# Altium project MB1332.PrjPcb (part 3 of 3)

## Sheet Power_Board.SchDoc: Board_Power
size A4; Date: Not used; ApprovedBy: Not used; CheckedBy: Not used; Author: Not used; CompanyName: STMicroelectronics; DrawnBy: Not used; Engineer: Not used; Organization: Not used; Address1: Not used; Address2: Not used; Address3: Not used; Address4: Not used; DocumentNumber: Not used; Revision: Not used; SheetNumber: 15; SheetTotal: 17
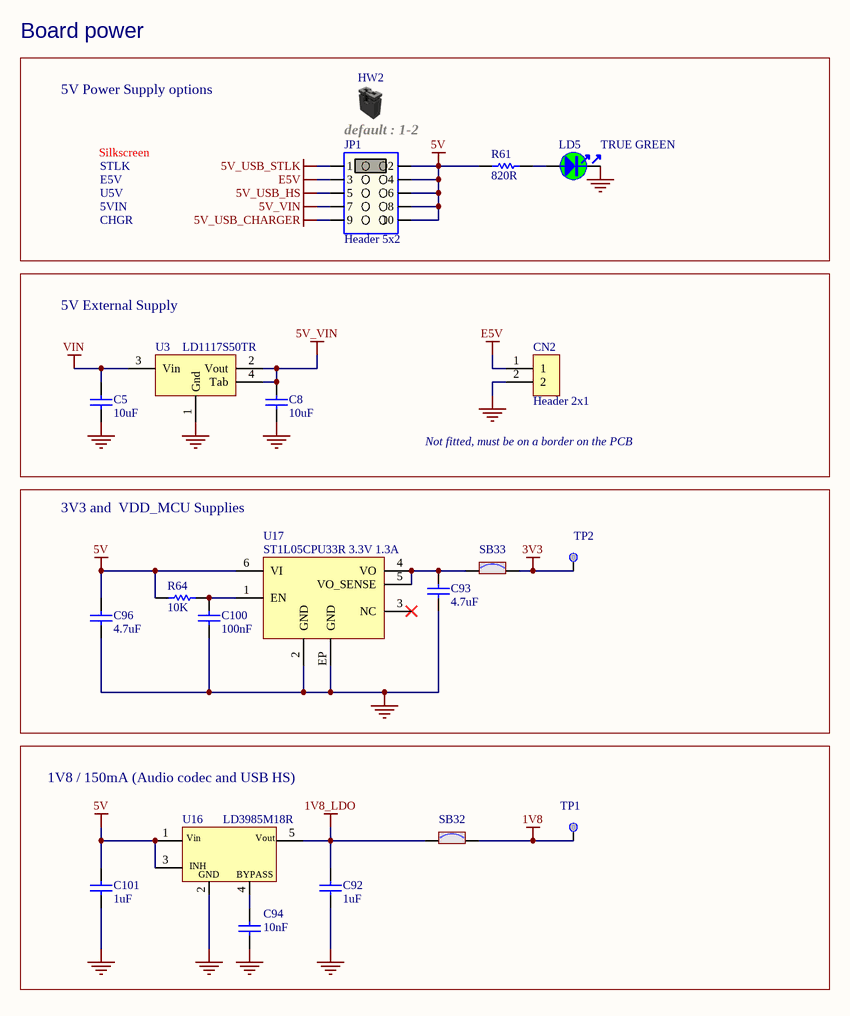
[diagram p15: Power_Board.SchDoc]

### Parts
C5  value 10uF  [C0805]  (hidden comment: Capacitor)
C8  value 10uF  [C0805]  (hidden comment: Capacitor)
C92  value 1uF  [C0402]  (hidden comment: Capacitor)
C93  value 4.7uF  [C0603]  (hidden comment: Capacitor)
C94  value 10nF  [C0402]  (hidden comment: Capacitor)
C96  value 4.7uF  [C0603]  (hidden comment: Capacitor)
C100  value 100nF  [C0402]  (hidden comment: Capacitor)
C101  value 1uF  [C0402]  (hidden comment: Capacitor)
CN2  Header 2x1  [CON_SAMTEC_TSW-102-07-G-S]
HW2  Shunt Black 2.54mm  (value not drawn)  (mechanical)
JP1  value Header 5x2  [CON_SAMTEC_TSM-105-01-L-DV]  (hidden comment: Jumper_Header 5x2 Fitted 1-2)
LD5  value TRUE GREEN  [LED_0603_VISHAY_VLMTG1300-GS08_GREEN_1A2K_H0P8]  (hidden comment: LED_green)
R61  value 820R  [R0603]  (hidden comment: Resistor)
R64  value 10K  [R0402]  (hidden comment: Resistor)
SB32  SB_ON  [SOLDER-BRIDGE_R0603-0R]  (value not drawn)
SB33  SB_ON  [SOLDER-BRIDGE_R0603-0R]  (value not drawn)
TP1  Test Point  [TP_SMD_2MM]  (value not drawn)  (no BOM)
TP2  Test Point  [TP_SMD_2MM]  (value not drawn)  (no BOM)
U3  LD1117S50TR  [REG_SOT223-TAB]
U16  LD3985M18R  [REG_SOT23-5L]
U17  value ST1L05CPU33R 3.3V 1.3A  [ICC_DFN6-EPAD_3X3_P095]  (hidden comment: ST1L05CPU33R)

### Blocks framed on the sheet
Board power: HW2 JP1 LD5 R61
5V External Supply: C5 C8 CN2 U3
3V3 and  VDD_MCU Supplies: C93 C96 C100 R64 SB33 TP2 U17
1V8 / 150mA (Audio codec and USB HS): C92 C94 C101 SB32 TP1 U16

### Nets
1V8: SB32.2 TP1.1
1V8_LDO: C92.2 SB32.1 U16.5(Vout)
3V3: SB33.2 TP2.1
5V: C96.2 C101.2 JP1.2 JP1.4 JP1.6 JP1.8 JP1.10 R61.1 R64.1 U16.1(Vin) U16.3(CE) U17.6(VI)
5V_USB_CHARGER: JP1.9
5V_USB_HS: JP1.5
5V_USB_STLK: JP1.1
5V_VIN: C8.2 JP1.7 U3.2(Vout) U3.4(Tab)
E5V: CN2.1 JP1.3
GND: C5.1 C8.1 C92.1 C93.1 C94.1 C96.1 C100.1 C101.1 CN2.2 LD5.2 U3.1(Gnd) U16.2(GND) U17.2(GND) U17.EP(GND)
VIN: C5.2 U3.3(Vin)
NetC93_2: C93.2 SB33.1 U17.4(VO) U17.5(VO_SENSE)
NetC94_2: C94.2 U16.4(BYPASS)
NetC100_2: C100.2 R64.2 U17.1(EN)
NetLD5_1: LD5.1 R61.2

Not connected (* = marked no-connect by the designer): U17 3(NC)*

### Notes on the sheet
- 5V Power Supply options
- Silkscreen
- default : 1-2
- STLK
- E5V
- U5V
- 5VIN
- CHGR
- Not fitted, must be on a border on the PCB

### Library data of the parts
C5 C8 = MCD-00014: Capacitor, MLCC, 10uF, 25V, X5R, 10%, 0805, T=0,85mm; Manufacturer_Part_Number: CC0805KRX5R8BB106; Manufacturer: YAGEO; Provided_By: SUBCO
C92 C101 = MCD-00095: Capacitor, MLCC, 1uF, 6V3, X5R, 10%, 0402, T=0,5mm; Manufacturer_Part_Number: GRM155R61E105KA12; Manufacturer: MURATA; Alternate_Manufacturer_Part_Number: GRM155R60J105KE19; Provided_By: SUBCO
C93 C96 = MCD-00009: Capacitor, MLCC, 4.7uF, 16V, X5R, 10%, 0603, T=0.8mm; Manufacturer_Part_Number: CC0603KRX5R7BB475; Manufacturer: YAGEO; Provided_By: SUBCO
C94 = MCD-00011: Capacitor, MLCC, 10nF, 16V, X7R, 10%, 0402, T=0.5mm; Manufacturer_Part_Number: CC0402KRX7R7BB103; Manufacturer: YAGEO; Provided_By: SUBCO
C100 = MCD-00006: Capacitor, MLCC, 100nF, 16V, X7R, 10%, 0402, T=0.5mm; Manufacturer_Part_Number: CC0402KRX7R7BB104; Manufacturer: YAGEO; Alternate_Manufacturer_Part_Number: GCM155R71C104KA55D; Alternate_Manufacturer: MURATA; Provided_By: SUBCO
CN2 = MCD-00032: Header, 2x1, 2,54mm, VR, TH, Height 5.84mm/2.54mm; Part_Type: Connector; Manufacturer_Part_Number: TSW-102-07-G-S; Manufacturer: SAMTEC; Alternate_Manufacturer_Part_Number: 313102S111116; Alternate_Manufacturer: JIUBABA; Part_Preference: Recommended
HW2 = MCD-00043: SHUNT 2.54mm BLACK; Part_Type: Mechanical; Manufacturer: SAMTEC; Alternate_Manufacturer_Part_Number: 316102S111A; Alternate_Manufacturer: JIUBABA; Value: SNT-100-BK-G; Provided_By: SUBCO
JP1 = MCD-01230: Header, 5x2, 2.54mm, VR, SMT, Height 5.84mm; Part_Type: Connector; Manufacturer_Part_Number: TSM-105-01-L-DV; Manufacturer: SAMTEC; Alternate_Manufacturer_Part_Number: PHFM25-1205G0B116T1; Alternate_Manufacturer: JIUBABA; Provided_By: SUBCO
LD5 = MCD-00589: LED Green, 0603 SMD, Fw Voltage = 2.8V - 3.6V; Part_Type: Display; Manufacturer_Part_Number: VLMTG1300-GS08; Manufacturer: VISHAY; Alternate_Manufacturer_Part_Number: LG Q396-PS-35; Alternate_Manufacturer: OSRAM OPTO SEMICONDUCTORS; Order_Code_RS: 7730452; Provided_By: SUBCO
R61 = MCD-00528: Resistor,820R,0603,1%,1/10W; Manufacturer_Part_Number: RC0603FR-07820RL; Manufacturer: YAGEO; BMS_Part_Number: 9129759; Provided_By: SUBCO
R64 = MCD-00053: Resistor,10K,0402,1%,1/16W; Manufacturer_Part_Number: RC0402FR-0710KL; Manufacturer: YAGEO; Provided_By: SUBCO
SB32 SB33 = MCD-00071: Solder Bridge ON; Part_Type: Mechanical; Manufacturer_Part_Number: RC0603JR-070RL; Manufacturer: YAGEO; Provided_By: SUBCO
TP1 TP2 = MCD-00177: Test Point 2mm; Part_Type: Mechanical
U3 = MCD-00088: IC REG LDO 5V 0.8A SOT223; Manufacturer: STMICROELECTRONICS; BMS_Part_Number: 9176133; Provided_By: SUBCO with ST control
U16 = MCD-00078: Ultra low drop-low noise BiCMOS voltage, regulators low ESR capacitors compatible; Manufacturer: STMICROELECTRONICS; Part_Type: IC; BMS_Part_Number: 9176159; Provided_By: SUBCO with ST control
U17 = MCD-01025: LDO, 3.3V, 1.3A, Very low quiescent current BiCMOS voltage regulator; Part_Type: IC; Manufacturer: STMICROELECTRONICS; BMS_Part_Number: 9176246; Provided_By: SUBCO with ST control

## Sheet Power_MCU.SchDoc: MCU_Power
size A4; Date: Not used; ApprovedBy: Not used; CheckedBy: Not used; Author: Not used; CompanyName: STMicroelectronics; DrawnBy: Not used; Engineer: Not used; Organization: Not used; Address1: Not used; Address2: Not used; Address3: Not used; Address4: Not used; DocumentNumber: Not used; Revision: Not used; SheetNumber: 14; SheetTotal: 17
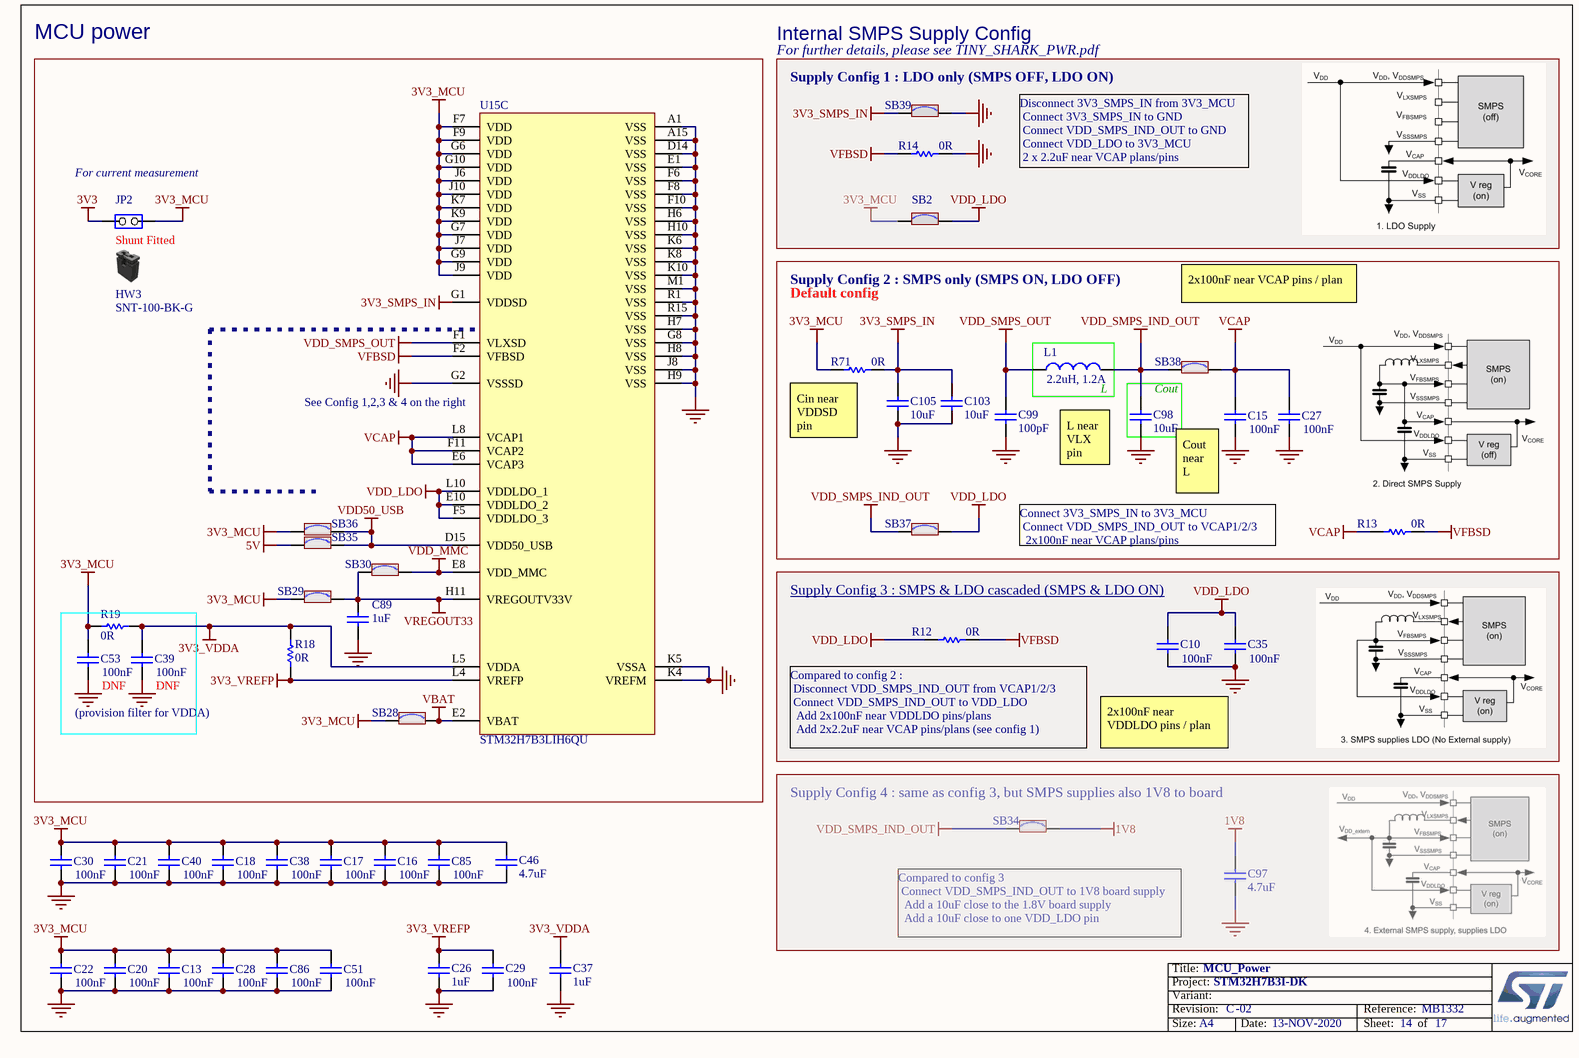
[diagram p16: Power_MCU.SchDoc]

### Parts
C10  value 100nF  [C0402]  (hidden comment: Capacitor)
C13  value 100nF  [C0402]  (hidden comment: Capacitor)
C15  value 100nF  [C0402]  (hidden comment: Capacitor)
C16  value 100nF  [C0402]  (hidden comment: Capacitor)
C17  value 100nF  [C0402]  (hidden comment: Capacitor)
C18  value 100nF  [C0402]  (hidden comment: Capacitor)
C20  value 100nF  [C0402]  (hidden comment: Capacitor)
C21  value 100nF  [C0402]  (hidden comment: Capacitor)
C22  value 100nF  [C0402]  (hidden comment: Capacitor)
C26  value 1uF  [C0402]  (hidden comment: Capacitor)
C27  value 100nF  [C0402]  (hidden comment: Capacitor)
C28  value 100nF  [C0402]  (hidden comment: Capacitor)
C29  value 100nF  [C0402]  (hidden comment: Capacitor)
C30  value 100nF  [C0402]  (hidden comment: Capacitor)
C35  value 100nF  [C0402]  (hidden comment: Capacitor)
C37  value 1uF  [C0402]  (hidden comment: Capacitor)
C38  value 100nF  [C0402]  (hidden comment: Capacitor)
C39  value 100nF  [C0402]  (hidden comment: Capacitor)
C40  value 100nF  [C0402]  (hidden comment: Capacitor)
C46  value 4.7uF  [C0603]  (hidden comment: Capacitor)
C51  value 100nF  [C0402]  (hidden comment: Capacitor)
C53  value 100nF  [C0402]  (hidden comment: Capacitor)
C85  value 100nF  [C0402]  (hidden comment: Capacitor)
C86  value 100nF  [C0402]  (hidden comment: Capacitor)
C89  value 1uF  [C0603]  (hidden comment: Capacitor)
C97  value 4.7uF  [C0603]  (hidden comment: Capacitor)
C98  value 10uF  [C0603]  (hidden comment: Capacitor)
C99  value 100pF  [C0402]  (hidden comment: Capacitor)
C103  value 10uF  [C0402]  (hidden comment: Capacitor)
C105  value 10uF  [C0402]  (hidden comment: Capacitor)
HW3  value SNT-100-BK-G  (hidden comment: Shunt Black 2.54mm)  (mechanical)
JP2  Jumper_Header 2x1  [CON_SAMTEC_TSW-102-07-G-S]  (value not drawn)
L1  value 2.2uH, 1.2A  [L0805_H0P9]  (hidden comment: Inductor)
R12  value 0R  [R0402]  (hidden comment: Resistor)
R13  value 0R  [R0402]  (hidden comment: Resistor)
R14  value 0R  [R0402]  (hidden comment: Resistor)
R18  value 0R  [R0603]  (hidden comment: Resistor)
R19  value 0R  [R0603]  (hidden comment: Resistor)
R71  value 0R  [R0603]  (hidden comment: Resistor)
SB2  SB_ON  [SOLDER-BRIDGE_R0603-0R]  (value not drawn)
SB28  SB_ON  [SOLDER-BRIDGE_R0603-0R]  (value not drawn)
SB29  SB_ON  [SOLDER-BRIDGE_R0603-0R]  (value not drawn)
SB30  SB_ON  [SOLDER-BRIDGE_R0603-0R]  (value not drawn)
SB34  SB_ON  [SOLDER-BRIDGE_R0603-0R]  (value not drawn)
SB35  SB_ON  [SOLDER-BRIDGE_R0603-0R]  (value not drawn)
SB36  SB_ON  [SOLDER-BRIDGE_R0603-0R]  (value not drawn)
SB37  SB_ON  [SOLDER-BRIDGE_R0603-0R]  (value not drawn)
SB38  SB_ON  [SOLDER-BRIDGE_R0603-0R]  (value not drawn)
SB39  SB_ON  [SOLDER-BRIDGE_R0603-0R]  (value not drawn)
U15  value STM32H7B3LIH6QU  [ICC_TFBGA225_13X13_STM32H7B3NIH6Q_P080]  (hidden comment: STM32H7B3NIH6Q)  (part C of 3)

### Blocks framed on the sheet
MCU power: C39 C53 C89 HW3 JP2 R18 R19 SB28-SB30 SB35 SB36 U15
Internal SMPS Supply Config: R14 SB2 SB39
L: L1
Cout: C98
Supply Config 3 : SMPS & LDO cascaded (SMPS & LDO ON): C10 C35 R12

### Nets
1V8: C97.2 SB34.1
3V3: JP2.1(COMMON)
3V3_MCU: C13.1 C16.1 C17.1 C18.1 C20.1 C21.1 C22.1 C28.1 C30.1 C38.1 C40.1 C46.2 C51.1 C53.1 C85.1 C86.1 JP2.2(NO) R19.1 R71.1 SB2.2 SB28.1 SB29.1 SB36.1 U15.F7(VDD) U15.F9(VDD) U15.G6(VDD) U15.G7(VDD) U15.G9(VDD) U15.G10(VDD) U15.J6(VDD) U15.J7(VDD) U15.J9(VDD) U15.J10(VDD) U15.K7(VDD) U15.K9(VDD)
3V3_SMPS_IN: C103.2 C105.2 R71.2 SB39.2 U15.G1(VDDSD)
3V3_VDDA: C37.2 C39.1 R18.1 R19.2 U15.L5(VDDA)
3V3_VREFP: C26.2 C29.2 R18.2 U15.L4(VREFP)
5V: SB35.1
GND: C10.1 C13.2 C15.2 C16.2 C17.2 C18.2 C20.2 C21.2 C22.2 C26.1 C27.2 C28.2 C29.1 C30.2 C35.1 C37.1 C38.2 C39.2 C40.2 C46.1 C51.2 C53.2 C85.2 C86.2 C89.1 C97.1 C98.1 C99.1 C103.1 C105.1 R14.2 SB39.1 U15.A1(VSS) U15.A15(VSS) U15.D14(VSS) U15.E1(VSS) U15.F6(VSS) U15.F8(VSS) U15.F10(VSS) U15.G2(VSSSD) U15.G8(VSS) U15.H6(VSS) U15.H7(VSS) U15.H8(VSS) U15.H9(VSS) U15.H10(VSS) U15.J8(VSS) U15.K4(VREFM) U15.K5(VSSA) U15.K6(VSS) U15.K8(VSS) U15.K10(VSS) U15.M1(VSS) U15.R1(VSS) U15.R15(VSS)
VBAT: SB28.2 U15.E2(VBAT)
VCAP: C15.1 C27.1 R13.1 SB38.1 U15.E6(VCAP3) U15.F11(VCAP2) U15.L8(VCAP1)
VDD50_USB: SB35.2 SB36.2 U15.D15(VDD50_USB)
VDD_LDO: C10.2 C35.2 R12.1 SB2.1 SB37.1 U15.E10(VDDLDO_2) U15.F5(VDDLDO_3) U15.L10(VDDLDO_1)
VDD_MMC: SB30.2 U15.E8(VDD_MMC)
VDD_SMPS_IND_OUT: C98.2 L1.2 SB34.2 SB37.2 SB38.2
VDD_SMPS_OUT: C99.2 L1.1 U15.F1(VLXSD)
VFBSD: R12.2 R13.2 R14.1 U15.F2(VFBSD)
VREGOUT33: C89.2 SB29.2 SB30.1 U15.H11(VREGOUTV33V)

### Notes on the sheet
- For further details, please see TINY_SHARK_PWR.pdf
- (near SB39) Supply Config 1 : LDO only (SMPS OFF, LDO ON)
- (near JP2) For current measurement
- Disconnect 3V3_SMPS_IN from 3V3_MCU
  Connect 3V3_SMPS_IN to GND
  Connect VDD_SMPS_IND_OUT to GND
  Connect VDD_LDO to 3V3_MCU
  2 x 2.2uF near VCAP plans/pins
- (near HW3) Shunt Fitted
- Default config
- Supply Config 2 : SMPS only (SMPS ON, LDO OFF)
- 2x100nF near VCAP pins / plan
- (near U15) See Config 1,2,3 & 4 on the right
- (near R71) Cin near VDDSD pin
- L near VLX pin
- (near C15) Cout near L
- Connect 3V3_SMPS_IN to 3V3_MCU
  Connect VDD_SMPS_IND_OUT to VCAP1/2/3
  2x100nF near VCAP plans/pins
- (provision filter for VDDA)
- DNF
- (near C39) DNF
- (near R12) Compared to config 2 :
  Disconnect VDD_SMPS_IND_OUT from VCAP1/2/3
  Connect VDD_SMPS_IND_OUT to VDD_LDO
  Add 2x100nF near VDDLDO pins/plans
  Add 2x2.2uF near VCAP pins/plans (see config 1)
- 2x100nF near VDDLDO pins / plan
- (near SB34) Supply Config 4 : same as config 3, but SMPS supplies also 1V8 to board
- Compared to config 3
  Connect VDD_SMPS_IND_OUT to 1V8 board supply
  Add a 10uF close to the 1.8V board supply
  Add a 10uF close to one VDD_LDO pin

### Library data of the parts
C10 C13 C15-C18 C20-C22 C27-C30 C35 C38-C40 C51 C53 C85 C86 = MCD-00006: as C100 on sheet Power_Board
C26 C37 = MCD-01722: Capacitor, 1uF, 10V, X5R, 10%, 0402, T=0.5mm; Manufacturer_Part_Number: CC0402KRX5R6BB105; Manufacturer: YAGEO; Provided_By: SUBCO
C46 = MCD-00009: as C93 on sheet Power_Board
C89 = MCD-00010: Capacitor, MLCC, 1uF, 16V, X5R, 10%, 0603, T=0,8mm; Manufacturer_Part_Number: CC0603KRX5R7BB105; Manufacturer: YAGEO; Provided_By: SUBCO
C97 = MCD-01121: Capacitor, MLCC, 4.7µF, 10V, X5R, 20%, 0603, T=0,8mm; Manufacturer_Part_Number: GRM188R61A475ME15; Manufacturer: MURATA; Provided_By: SUBCO
C98 = MCD-00243: Capacitor, MLCC, 10uF, 6V3, X5R, 10%, 0603, T=0,8mm; Manufacturer_Part_Number: CC0603KRX5R5BB106; Manufacturer: YAGEO; Provided_By: SUBCO
C99 = MCD-00205: Capacitor, MLCC, 100pF, 50V, NPO, 5%, 0402, T=0,5mm; Manufacturer_Part_Number: CC0402JRNPO9BN101; Manufacturer: YAGEO; Provided_By: SUBCO
C103 C105 = MCD-01716: Capacitor, MLCC, 10uF, 6V3, X5R, 20%, 0402, T=0.5mm; Manufacturer_Part_Number: CC0402MRX5R5BB106; Manufacturer: YAGEO; Provided_By: SUBCO
HW3 = MCD-00043: SHUNT 2.54mm BLACK; Manufacturer: SAMTEC; Part_Type: Mechanical; Alternate_Manufacturer_Part_Number: 316102S111A; Alternate_Manufacturer: JIUBABA; Provided_By: SUBCO
JP2 = MCD-00045: Header, 2x1, 2,54mm, VR, TH, Height 5.84mm/2.54mm; Manufacturer_Part_Number: TSW-102-07-x-S; Manufacturer: SAMTEC; Part_Type: Connector; Alternate_Manufacturer_Part_Number: 313102S111116; Alternate_Manufacturer: JIUBABA; Value: Shunt not fitted; Provided_By: SUBCO
L1 = MCD-01340: Inductor, 2.2uH, 20%, Isat 1.2A, DCR 0.228Ohm, 0805; Manufacturer_Part_Number: DFE201210U-2R2M=P2; Manufacturer: MURATA; Provided_By: SUBCO
R12-R14 = MCD-00052: Resistor,0R,0402,5%,1/16W; Manufacturer_Part_Number: RC0402JR-070RL; Manufacturer: YAGEO; Provided_By: SUBCO
R18 R19 R71 = MCD-00056: Resistor,0R,0603,5%,1/10W; Manufacturer_Part_Number: RC0603JR-070RL; Manufacturer: YAGEO; Provided_By: SUBCO
SB2 SB28-SB30 SB34-SB39 = MCD-00071: as SB32 on sheet Power_Board
U15 = MCD-02002: STM32H7B3LIH6QU (crypto) - FG: 32H7B3LIH6QU$P2 Cut1.1, TFBGA225 13x13x0.8; Part_Type: IC; Manufacturer: STMICROELECTRONICS; ECCN_US: 5A992C; ECCN_EU: 5A002A4; Provided_By: SUBCO with ST control

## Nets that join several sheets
1V8: Audio_Codec (8 pins), Peripherals (U5.2), USB_OTG_HS_externalPHY (C108.1 U20.28 U20.30), Power_Board (SB32.2 TP1.1), Power_MCU (C97.2 SB34.1)
3V3: Audio_Codec (R55.2 R56.2 SB20.1), Camera (C63.2 C64.2 CN7.20 CN7.30), FDCAN (C59.1 U4.5), LCD (C1.1 CN1.50), Memory (15 pins), OCSPI (8 pins), Peripherals (8 pins), SDcard (8 pins), USB_OTG_HS_externalPHY (10 pins), MCU (R51.1 SW1.2), Arduino (CN19.2 CN19.4 R1.2), JTAG (CN12.1), STLink_V3E_SWD (CN8.3 R77.2), Power_Board (SB33.2 TP2.1), Power_MCU (JP2.1)
3V3_VREFP: Arduino (C79.1 R45.2), Power_MCU (C26.2 C29.2 R18.2 U15.L4)
5V: FDCAN (C45.1 U4.3), LCD (R3.1), Peripherals (P1.6 P1.15 U5.42), USB_OTG_HS_externalPHY (C117.1 U20.21 U25.5), Arduino (CN19.5), STLink_V3E_SWD (R79.1), Power_Board (12 pins), Power_MCU (SB35.1)
5V_USB_CHARGER: STLink_V3E_SWD (8 pins), Power_Board (JP1.9)
5V_USB_HS: USB_OTG_HS_externalPHY (R84.2), STLink_V3E_SWD (D3.1), Power_Board (JP1.5)
5V_USB_STLK: STLink_V3E_SWD (C119.1 U24.1), Power_Board (JP1.1)
5V_VIN: Arduino (R114.2), STLink_V3E_SWD (D1.1), Power_Board (C8.2 JP1.7 U3.2 U3.4)
GND: Audio_Codec (27 pins), Camera (7 pins), FDCAN (5 pins), LCD (13 pins), Memory (15 pins), OCSPI (6 pins), Peripherals (15 pins), SDcard (11 pins), USB_OTG_HS_externalPHY (27 pins), MCU (12 pins), Arduino (6 pins), JTAG (CN12.3 CN12.5 U11.2 U12.2), STLink_V3E_SWD (100 pins), Power_Board (14 pins), Power_MCU (55 pins)
VIN: Arduino (CN19.8), Power_Board (C5.2 U3.3)
2_CTS: Peripherals (SB6.1 SB25.2), MCU (SB31.1 U15.P1)
2_RTS: Peripherals (SB13.1 SB23.2), MCU (U15.A11)
2_RX: Peripherals (SB11.1 SB21.2), MCU (U15.B10)
2_TX: Peripherals (SB9.1 SB18.2), MCU (U15.C10)
A0: Memory (U14.H7), MCU (U15.G4)
A1: Memory (U14.H8), MCU (U15.G3)
A2: Memory (U14.J8), MCU (U15.H1)
A3: Memory (U14.J7), MCU (U15.J1)
A4: Memory (U14.J3), MCU (U15.H3)
A5: Memory (U14.J2), MCU (U15.J2)
A6: Memory (U14.H3), MCU (U15.R9)
A7: Memory (U14.H2), MCU (U15.M8)
A8: Memory (U14.H1), MCU (U15.P9)
A9: Memory (U14.G3), MCU (U15.N9)
A10: Memory (U14.H9), MCU (U15.R10)
A11: Memory (U14.G2), MCU (U15.P10)
A14: Memory (U14.G7), MCU (U15.H12)
A15: Memory (U14.G8), MCU (U15.G14)
ARD_A0: MCU (SB45.2), Arduino (CN20.1)
ARD_A1: MCU (U15.M6), Arduino (CN20.2)
ARD_A2: MCU (U15.P3), Arduino (CN20.3)
ARD_A3: MCU (U15.R3), Arduino (CN20.4)
ARD_A4: MCU (U15.N1), Arduino (SB52.1)
ARD_A5: MCU (U15.N2), Arduino (SB54.1)
ARD_D0: MCU (U15.B15), Arduino (CN11.1)
ARD_D1: MCU (U15.D13), Arduino (CN11.2)
ARD_D2: MCU (U15.E3), Arduino (CN11.3)
ARD_D3: MCU (U15.N13), Arduino (CN11.4)
ARD_D4: MCU (U15.E5), Arduino (CN11.5)
ARD_D5: MCU (U15.P15), Arduino (CN11.6)
ARD_D6: MCU (U15.M12), Arduino (CN11.7)
ARD_D7: MCU (U15.F3), Arduino (CN11.8)
ARD_D8: MCU (U15.M3), Arduino (CN10.1)
ARD_D9: MCU (U15.D4), Arduino (CN10.2)
ARD_D10: MCU (U15.C13), Arduino (CN10.3)
AUDIO_NRST: Audio_Codec (R44.2 U13.25), MCU (U15.G15)
CKOUT: Peripherals (CN3.3 CN3.4), MCU (SB50.2)
D0: Memory (U14.A8), MCU (U15.K12)
D1: Memory (U14.B9), MCU (U15.K13)
D2: Memory (U14.B8), MCU (U15.C11)
D3: Memory (U14.C9), MCU (U15.A12)
D4: Memory (U14.C8), MCU (U15.M9)
D5: Memory (U14.D9), MCU (U15.R11)
D6: Memory (U14.D8), MCU (U15.P11)
D7: Memory (U14.E9), MCU (U15.N11)
D8: Memory (U14.E1), MCU (U15.R12)
D9: Memory (U14.D2), MCU (U15.L9)
D10: Memory (U14.D1), MCU (U15.M10)
D11: Memory (U14.C2), MCU (U15.N10)
D12: Memory (U14.C1), MCU (U15.P12)
D13: Memory (U14.B2), MCU (U15.L12)
D14: Memory (U14.B1), MCU (U15.N15)
D15: Memory (U14.A2), MCU (U15.L13)
DCMI_D0: Camera (CN7.4), Peripherals (P1.11), MCU (U15.F14)
DCMI_D1: Camera (CN7.5), Peripherals (CN3.7 P1.17), MCU (U15.E15)
DCMI_D2: Camera (CN7.6), MCU (U15.A8)
DCMI_D3: Camera (CN7.7), SDcard (CN4.8 R9.1 U10.5 U10.6), MCU (U15.E14)
DCMI_D4: Camera (CN7.8), SDcard (CN4.2 R6.1 U9.2 U9.9), MCU (U15.D11)
DCMI_D5: Camera (CN7.9), Peripherals (P1.18), MCU (U15.D10)
DCMI_D6: Camera (CN7.10), Peripherals (P1.20), MCU (U15.B4)
DCMI_D7: Camera (CN7.11), Peripherals (CN3.5 P1.19), MCU (U15.A3)
DCMI_HSYNC: Camera (CN7.17), MCU (SB44.1 SB45.1 U15.L6)
DCMI_PIXCLK: Camera (CN7.15), MCU (U15.P5)
DCMI_PWR_EN: Camera (CN7.25), MCU (U15.R5)
DCMI_VSYNC: Camera (CN7.19), MCU (U15.D6)
DETECTn: Peripherals (CN3.10), MCU (U15.C3)
DFSDM1_2_DATIN1: Peripherals (CN3.6), MCU (SB48.2)
EXT_RESET: Peripherals (CN16.5), MCU (U15.A4)
FDCAN_RX: FDCAN (U4.4), MCU (SB3.1)
FDCAN_STBY: FDCAN (R20.1 U4.8), MCU (SB5.1)
FDCAN_TX: FDCAN (U4.1), MCU (SB4.1)
FMC_NBL0: Memory (U14.E8), MCU (U15.B3)
FMC_NBL1: Memory (U14.F1), MCU (U15.C4)
I2C4_SCL: Audio_Codec (R56.1 U13.3), Camera (CN7.28), LCD (CN1.40), MCU (U15.L15)
I2C4_SDA: Audio_Codec (R55.1 U13.2), Camera (CN7.27), LCD (CN1.38), MCU (U15.K11)
I2S6_CK: Audio_Codec (R52.2), MCU (U15.D8)
I2S6_MCK: Audio_Codec (R48.2), MCU (SB46.2)
I2S6_SDI: Audio_Codec (R47.2), MCU (U15.C8)
I2S6_SDO: Audio_Codec (R60.2), MCU (U15.A7)
I2S6_WS: Audio_Codec (R54.2), MCU (SB31.2)
JTDI: MCU (U15.C12), JTAG (R36.2)
LCD_B0: LCD (CN1.21), MCU (U15.E9)
LCD_B1: LCD (CN1.23), MCU (U15.D9)
LCD_B2: LCD (CN1.25), MCU (U15.C9)
LCD_B3: LCD (CN1.27), MCU (U15.B9)
LCD_B4: LCD (CN1.29), MCU (U15.B7)
LCD_B5: LCD (CN1.31), MCU (U15.C7)
LCD_B6: LCD (CN1.33), MCU (U15.A6)
LCD_B7: LCD (CN1.35), MCU (U15.B6)
LCD_BL_CTRL: LCD (CN1.43), MCU (U15.P2)
LCD_CLK: LCD (CN1.32), MCU (U15.H4)
LCD_DE: LCD (CN1.22), MCU (U15.D7)
LCD_G0: LCD (CN1.4), MCU (U15.K15)
LCD_G1: LCD (CN1.6), MCU (U15.J15)
LCD_G2: LCD (CN1.8), MCU (U15.J14)
LCD_G3: LCD (CN1.10), MCU (U15.J13)
LCD_G4: LCD (CN1.12), MCU (U15.J11)
LCD_G5: LCD (CN1.14), MCU (U15.J12)
LCD_G6: LCD (CN1.16), MCU (U15.H15)
LCD_G7: LCD (CN1.18), MCU (U15.H14)
LCD_HSYNC: LCD (CN1.26), MCU (U15.H2)
LCD_INT: LCD (CN1.39), MCU (U15.M4)
LCD_ON/OFF: LCD (CN1.24), MCU (U15.R2)
LCD_R0: LCD (CN1.3), MCU (U15.M7)
LCD_R1: LCD (CN1.5), MCU (U15.N7)
LCD_R2: LCD (CN1.7), MCU (U15.P7)
LCD_R3: LCD (CN1.9), MCU (U15.R7)
LCD_R4: LCD (CN1.11), MCU (U15.R8)
LCD_R5: LCD (CN1.13), MCU (U15.P8)
LCD_R6: LCD (CN1.15), MCU (U15.N12)
LCD_R7: LCD (CN1.17), MCU (U15.K14)
LCD_VSYNC: LCD (CN1.28), MCU (U15.H5)
MCO1: Camera (R25.1), MCU (U15.G11)
MEMS_LED: Peripherals (CN3.12), MCU (U15.B14)
MISO: Peripherals (SB10.1 SB19.1), MCU (U15.J5)
MOSI: Peripherals (SB8.1 SB26.1), MCU (U15.N3)
NJTRST: MCU (U15.B5), JTAG (R39.2)
nSS: Peripherals (SB7.1 SB24.1), MCU (SB3.2 U15.C15)
OCSPI1_CLK: OCSPI (U27.B2), MCU (R111.1)
OCSPI1_DQS: OCSPI (U27.C3), MCU (R91.1)
OCSPI1_IO0: OCSPI (U27.D3), MCU (R106.2)
OCSPI1_IO1: OCSPI (U27.D2), MCU (R109.2)
OCSPI1_IO2: OCSPI (U27.C4), MCU (R92.2)
OCSPI1_IO3: OCSPI (U27.D4), MCU (R94.2)
OCSPI1_IO4: OCSPI (U27.D5), MCU (R93.1)
OCSPI1_IO5: OCSPI (U27.E3), MCU (R107.1)
OCSPI1_IO6: OCSPI (U27.E2), MCU (R108.1)
OCSPI1_IO7: OCSPI (U27.E1), MCU (R110.2)
OCSPI1_NCS: OCSPI (R113.2 U27.C2), MCU (R112.1)
OSC_24M: Camera (R26.1), USB_OTG_HS_externalPHY (SB41.2)
PA12: Peripherals (SB12.1 SB22.1), MCU (SB4.2 U15.C14)
PH8: Peripherals (P1.12), MCU (SB5.2 U15.P14)
PMOD8-MOSIs: Peripherals (P1.8), MCU (U15.M15)
PMOD9: Peripherals (P1.9), MCU (U15.M14)
PMOD13-ADC: Peripherals (P1.13), MCU (SB44.2)
PMOD14-PWM: Peripherals (P1.14), MCU (U15.K1)
SAI1_FS_A: Audio_Codec (R53.2), MCU (U15.C2)
SAI1_MCLK_A: Audio_Codec (R49.2), MCU (U15.G12)
SAI1_SCK_A: Audio_Codec (R50.2), MCU (U15.D3)
SAI1_SD_A: Audio_Codec (R59.2), MCU (U15.E4)
SAI1_SD_B: Audio_Codec (R46.2), MCU (U15.B1)
SDCKE1: Memory (R67.2), MCU (U15.R14)
SDCLK: Memory (U14.F2), MCU (U15.F15)
SDIO1_CK: SDcard (CN4.5 U10.2 U10.9), MCU (U15.B12)
SDIO1_CMD: SDcard (CN4.3 R7.1 U10.1 U10.10), MCU (U15.B11)
SDIO1_D0: SDcard (CN4.7 R8.1 U10.4 U10.7), MCU (U15.F13)
SDIO1_D2: SDcard (CN4.1 R5.1 U9.1 U9.10), MCU (U15.A13)
SDNCAS: Memory (U14.F7), MCU (U15.A5)
SDNE1: Memory (U14.G9), MCU (U15.M11)
SDNRAS: Memory (U14.F8), MCU (U15.N8)
SDNWE: Memory (U14.F9), MCU (U15.P4)
T_NRST: Camera (CN7.26), LCD (CN1.36), OCSPI (SB51.1), Peripherals (SB15.2), USB_OTG_HS_externalPHY (SB40.2), MCU (5 pins), Arduino (CN19.3), JTAG (R38.2), STLink_V3E_SWD (CN8.12 R29.1 U7.5)
T_SWCLK: MCU (U15.B13), JTAG (R41.2), STLink_V3E_SWD (CN8.6 CN9.1 R32.1 U7.3)
T_SWDIO: MCU (U15.E12), JTAG (R40.2), STLink_V3E_SWD (CN8.4 CN9.2 R30.1 U7.4)
T_SWO: MCU (U15.C6), JTAG (R37.2), STLink_V3E_SWD (CN8.8 R31.1 U7.1)
ULPI_CK: USB_OTG_HS_externalPHY (U20.1), MCU (U15.N5)
ULPI_D0: USB_OTG_HS_externalPHY (U20.3), MCU (SB46.1 U15.R4)
ULPI_D1: USB_OTG_HS_externalPHY (U20.4), MCU (SB47.2)
ULPI_D2: USB_OTG_HS_externalPHY (U20.5), MCU (U15.L7)
ULPI_D3: USB_OTG_HS_externalPHY (U20.6), MCU (U15.R13)
ULPI_D4: USB_OTG_HS_externalPHY (U20.7), MCU (U15.P13)
ULPI_D5: USB_OTG_HS_externalPHY (U20.9), MCU (SB49.2)
ULPI_D6: USB_OTG_HS_externalPHY (U20.10), MCU (U15.M13)
ULPI_D7: USB_OTG_HS_externalPHY (U20.13), MCU (U15.E7)
ULPI_DIR: USB_OTG_HS_externalPHY (U20.31), MCU (U15.G5)
ULPI_NXT: USB_OTG_HS_externalPHY (U20.2), MCU (U15.M5)
ULPI_STP: USB_OTG_HS_externalPHY (U20.29), MCU (U15.L3)
USB_OTG_HS_OVCR: USB_OTG_HS_externalPHY (LD8.2 R102.1 U25.3), MCU (U15.L11)
uSD_Detect: SDcard (CN4.10 R24.1), MCU (U15.C1)
USER_LED1: Peripherals (R10.2), MCU (U15.B8)
USER_LED2: Peripherals (R4.2), MCU (U15.H13)
WAKEUP: Peripherals (5 pins), MCU (U15.F4)
WIFI_BOOT: Peripherals (U5.39), MCU (U15.A14)
WIFI_DATRDY: Peripherals (SB27.1), MCU (U15.B2)
WIFI_GPIO: Peripherals (SB17.2), MCU (U15.A2)
WIFI_RST: Peripherals (SB16.2), MCU (U15.E11)
WIFI_WKUP: Peripherals (SB14.2), MCU (U15.D12)

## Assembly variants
H7B3I: not fitted C39 C53 C97 C99 C102 C122 CN9 CN12 CN13 CN17 R12 R14 R24 R45 R58 R65 R88 R100 R101 SB2 SB3 SB4 SB5 SB6 SB7 SB8 SB9 SB10 SB11 SB12 SB13 SB15 SB18 SB21 SB23 SB25 SB34 SB35 SB39 SB40 SB42 SB43 SB53 SB55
